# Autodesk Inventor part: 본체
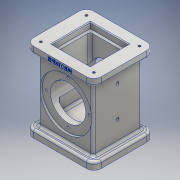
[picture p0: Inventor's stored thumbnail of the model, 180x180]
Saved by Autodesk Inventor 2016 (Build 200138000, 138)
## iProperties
Created: 2017-08
Part Number: 본체
Material: 알루미늄 6061
Document SubType Name: Modeling
Designer: USER
Mass: 790.515 g
Surface Area: 623.184 cm^2
Volume: 292.783 cm^3
Density: 2.7 g/cm^3
Appearance: 알루미늄 - 평지
Author: USER
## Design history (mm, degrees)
sketch "스케치1"
  geometry: L1 (0, 0)-(0, 10); L2 (0, 10)-(8, 10); L3 (8, 10)-(8, 98); L4 (8, 98)-(0, 98); L5 (0, 98)-(0, 108); L6 (0, 108)-(82, 108); L7 (82, 108)-(82, 98); L8 (82, 98)-(74, 98); L9 (74, 98)-(74, 10); L10 (74, 10)-(82, 10); L11 (82, 10)-(82, 0); L12 (82, 0)-(0, 0); L13 (8, 10)-(74, 10); L14 (8, 98)-(74, 98)
  constraints: 28 end point, 8 perpendicular, 4 point on line, 2 horizontal, 1 vertical
  dimensions: "d0" = 108 distance between parallel lines of L12 L6; "d1" = 10 distance between parallel lines of L4 L6; "d2" = 10 distance between parallel lines of L12 L2; "d7" = 8 distance of L3.end L4.end; "d11" = 82 distance between parallel lines of L7 L5; "d12" = 82 distance between parallel lines of L11 L1; "d13" = 66 distance between parallel lines of L3 L9; "d14" = 10 distance between parallel lines of L6 L8
extrude "돌출5" new body sketch "스케치1" stored distance "d73" = 74; taper "d74" = 0 deg
extrude "돌출6" join sketch "스케치1" stored distance "d75" = 92; taper "d76" = 0 deg
sketch "스케치12"
  geometry: 1 further point
node "작업 평면4"
sketch "스케치13"
  geometry: L1 (8, 10)-(8, 98) reference; L2 (8, 54)-(74, 54); L3 (74, 98)-(74, 10) reference; L4 (8, 54)-(8, 89); L5 (8, 89)-(11, 89); L6 (11, 89)-(11, 78); L7 (11, 78)-(71, 78); L8 (71, 78)-(71, 89); L9 (71, 89)-(74, 89); L10 (74, 89)-(74, 54); 1 further point
  constraints: 16 end point, 4 point on line, 3 perpendicular, 2 midpoint, 1 collinear, 1 horizontal
  dimensions: "d78" = 3 distance of L4.end L5.end; "d79" = 3 distance of L8.end L9.end; "d80" = 48 diameter of L7 L2; "d81" = 70 diameter of L5.end L2
revolve "회전2" sketch "스케치13" stored, may be unused: angle "d82" = 90 deg
sketch "스케치14"
  geometry: L1 (24, 19)-(68, 19); L2 (68, 19)-(68, 63); L3 (68, 63)-(24, 63); L4 (24, 63)-(24, 19); L5 (20, 15)-(72, 15); L6 (72, 15)-(72, 67); L7 (72, 67)-(20, 67); L8 (20, 67)-(20, 15); L9 (0, 0)-(0, 82) reference; L10 (0, 0)-(92, 0) reference; 8 further points
  constraints: 16 end point, 7 midpoint, 4 parallel, 2 horizontal, 2 horizontal alignment, 2 perpendicular, 2 vertical alignment
  dimensions: "d83" = 52 distance of L7.end L5.start; "d84" = 52 distance of L6.end L7.end; "d85" = 44 distance of L3.end L1.start; "d86" = 44 distance of L1.start L1.end
extrude "돌출7" cut sketch "스케치14" distance "d87" = 8; taper "d88" = 0 deg
extrude "돌출8" cut sketch "스케치14" distance "d89" = 82; taper "d90" = 0 deg
sketch "스케치15"
  geometry: L1 (22, -65)-(70, -65); L2 (70, -65)-(70, -17); L3 (70, -17)-(22, -17); L4 (22, -17)-(22, -65); L5 (0, -82)-(0, 0) reference; L6 (0, -82)-(92, -82) reference; 5 further points
  constraints: 8 end point, 4 midpoint, 2 parallel, 1 horizontal, 1 horizontal alignment, 1 perpendicular, 1 vertical alignment
  dimensions: "d91" = 48 distance of L3.end L1.start; "d92" = 48 distance of L2.end L3.end
extrude "돌출9" cut sketch "스케치15" distance "d93" = 16; taper "d94" = 0 deg
sketch "스케치16"
  geometry: L1 (10, 72)-(82, 72); L2 (82, 72)-(82, 10); L3 (82, 10)-(10, 10); L4 (10, 10)-(10, 72); L5 (0, 82)-(92, 82) reference; L6 (0, 0)-(0, 82) reference; 9 further points
  constraints: 8 end point, 4 coincident, 4 midpoint, 2 parallel, 1 horizontal, 1 horizontal alignment, 1 perpendicular, 1 vertical alignment
  dimensions: "d95" = 72 distance of L1.start L1.end; "d96" = 62 distance of L3.end L1.start
hole "구멍4" sketch "스케치16" at (10, 72), (10, 10), (82, 10), (82, 72) diameter "d97" = 3.242; stored, may be unused: countersink angle "d101" = 90 deg, drill point angle "d103" = 118 deg; dims "d98" = 4, "d99" = 4, "d100" = 2, "d102" = 6
node "작업 평면5"
sketch "스케치17" dims "d104" = 58
  geometry: C1 r 35 at (0, 0) reference; 3 further points
  constraints: 1 coincident, 1 vertical alignment, 2 other
hole "구멍5" sketch "스케치17" at (0, 29) diameter "d105" = 3.242; stored, may be unused: countersink angle "d109" = 90 deg, drill point angle "d111" = 118 deg; dims "d106" = 4, "d107" = 4, "d108" = 2, "d110" = 6
node "작업 평면6"
sketch "스케치18"
  geometry: L1 (-108, 82)-(-108, 0) reference; L2 (0, 0)-(0, 82) reference; 4 further points
  constraints: 2 horizontal alignment, 2 midpoint
  dimensions: "d115" = 38 distance from line of L2 point (-38, 41); "d116" = 42 distance of point (-38, 41) point (-80, 41)
hole "구멍6" sketch "스케치18" at (-80, 41), (-38, 41) diameter "d117" = 4.134; stored, may be unused: countersink angle "d121" = 90 deg, drill point angle "d123" = 118 deg; dims "d118" = 20, "d119" = 4, "d120" = 2, "d122" = 20
fillet "모깎기2" dims "d124" = 10
chamfer "모따기2" distance "d125" = 1; stored, may be unused: second distance "d126" = 2, angle "d127" = 45 deg
fillet "모깎기3" dims "d128" = 3
fillet "모깎기4" dims "d129" = 3
fillet "모깎기5" dims "d130" = 3
fillet "모깎기6" dims "d131" = 3
sketch "스케치19"
  geometry: L1 (0, 0)-(72, 0) reference; L2 (-10, 0)-(-10, -7) reference; 2 further points
  constraints: 1 other
  dimensions: "d132" = 4 distance from line of L1 point (36, -4); "d133" = 46 distance from line of L2 point (36, -4)
feature "엠보싱2" sketch "스케치19" dims "d0" = 108, "d1" = 10, "d2" = 10, "d7" = 8, "d11" = 82, "d12" = 82, "d13" = 66, "d14" = 10, "d134" = 0.5, "d135" = 0
fillet "모깎기7" dims "d136" = 3
fillet "모깎기8" dims "d137" = 3
node "솔리드2"
mirror "대칭3"
pattern_circular "원형 패턴2" dims angle "d113" = 360 deg
mirror "대칭4"
other parameters: "d77" = 0
